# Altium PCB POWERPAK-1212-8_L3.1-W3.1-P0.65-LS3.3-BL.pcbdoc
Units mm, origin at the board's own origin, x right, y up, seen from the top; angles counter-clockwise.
Board outline 15.94 x 16.68 mm, 2 copper layers (Top Layer, Bottom Layer), stack 0 mm thick; 1 components, 0 nets, 9 pads, 0 vias.
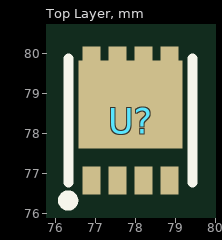
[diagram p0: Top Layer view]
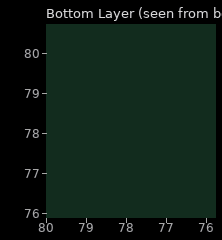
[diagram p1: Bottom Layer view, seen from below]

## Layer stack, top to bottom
Top Layer: signal copper (thickness not stored)
Bottom Layer: signal copper (thickness not stored)

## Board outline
85.787,69.85 69.85,69.85 69.85,86.527 85.787,86.527

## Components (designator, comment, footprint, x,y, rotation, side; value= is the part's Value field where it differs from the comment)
U? "" POWERPAK-1212-8_L3.1-W3.1-P0.65-LS3.3-BL 77.887,78.327 r0 top

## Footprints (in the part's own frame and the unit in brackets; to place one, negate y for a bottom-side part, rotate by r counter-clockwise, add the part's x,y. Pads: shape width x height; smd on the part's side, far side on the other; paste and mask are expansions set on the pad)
POWERPAK-1212-8_L3.1-W3.1-P0.65-LS3.3-BL [mm]
  rect 0.45x0.7 smd paste-100 mask+0.051: 1(-0.975,-1.5) 2(-0.325,-1.5) 3(0.325,-1.5) 4(0.975,-1.5) 5(0.975,1.5) 6(0.325,1.5) 7(-0.325,1.5) 8(-0.975,1.5)
  rect 2.6x2.2 smd paste-100 mask+0.051: 8(0,0.4)
  silkscreen extent -1.69,-2.13 1.55,1.55

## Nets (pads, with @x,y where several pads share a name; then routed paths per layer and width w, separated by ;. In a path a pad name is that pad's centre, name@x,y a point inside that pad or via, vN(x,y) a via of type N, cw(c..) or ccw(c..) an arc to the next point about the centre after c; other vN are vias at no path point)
pads on no net: U?.1 U?.2 U?.3 U?.4 U?.5 U?.6 U?.7 U?.8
